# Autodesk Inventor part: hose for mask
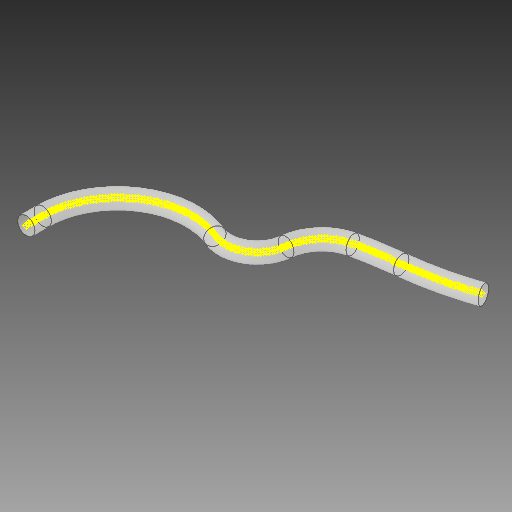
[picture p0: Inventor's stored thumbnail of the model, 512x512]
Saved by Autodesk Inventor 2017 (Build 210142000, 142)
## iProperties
Created: 2020-03
Part Number: hose for mask
Material: Polycarbonate, Clear
Document SubType Name: Modeling
Designer: user
Density: 1.2 g/cm^3
Appearance: Polycarbonate - Clear
Mass: 16.5377 g
Surface Area: 919.247 cm^2
Volume: 13.7814 cm^3
Author: user
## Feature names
1. Rectangular Pattern1
2. Sweep2
## Parameters: d1 = 25 mm, d2 = 25.4 mm, d7 = 3.16094 mm, d8 = 0.3 mm, d9 = 0, d10 = 0
